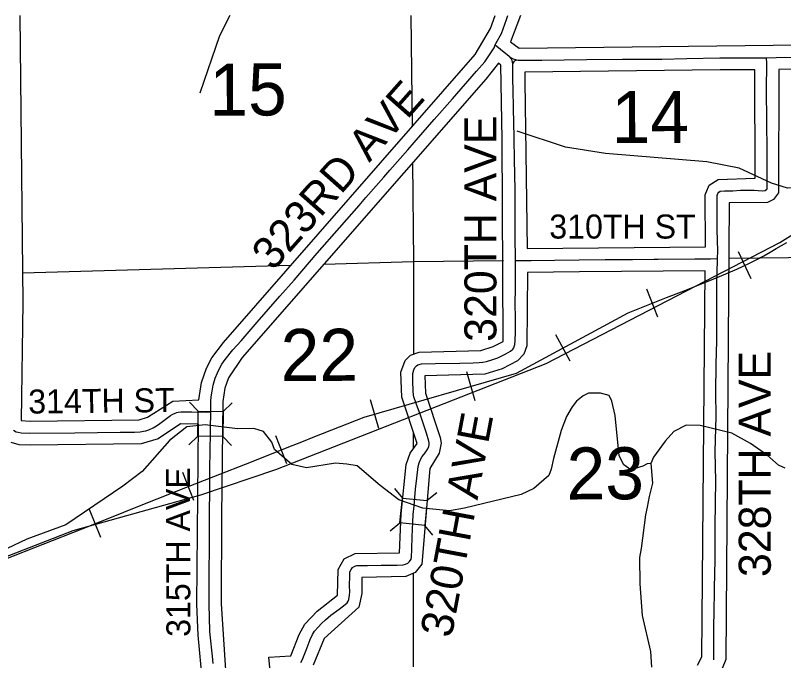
# Model space of a CAD drawing. Extents: x 10133 to 81668, y 7924 to 11018.
# Drawn here: x 11756.3 to 12044.1, y 9353.2 to 9594.9 of the extents above; entities that cross this region are included whole.
import ezdxf

# ---------------------------------------------------------------- set-up
doc = ezdxf.new("R2010")
doc.units = 0
for name, color, linetype in [('tdCoCityStreetMajor', 7, 'Continuous'), ('tdCoCityStreetMinor', 7, 'Continuous'), ('tdCoHydroRiver', 7, 'Continuous'), ('tdCoPriNonDiv', 7, 'Continuous'), ('tdCoRRCL', 7, 'Continuous'), ('tdCoRROwnerTxt', 7, 'Continuous'), ('tdCoSecRteBand', 7, 'Continuous'), ('tdCoShieldCoRte', 7, 'Continuous'), ('tdCoShieldStRte', 7, 'Continuous'), ('tdCoStrucNonDivPri', 7, 'Continuous')]:
    doc.layers.add(name, color=color, linetype=linetype)

msp = doc.modelspace()

# ---------------------------------------------------------------- linework, layer by layer
at = {"layer": 'tdCoCityStreetMajor'}
for points in [[(12019.3, 9503.87), (12019.38, 9506.61), (12019.18, 9514.65), (12019.13, 9517.56), (12019.21, 9525.57), (12019.18, 9527.39), (12019.38, 9528.13), (12019.8, 9528.73), (12020.32, 9529.02), (12021.89, 9529.17), (12025, 9529.22), (12027.98, 9529.37), (12033.04, 9529.39), (12036.05, 9529.22), (12037.18, 9529.24), (12037.87, 9529.89), (12037.87, 9533.71), (12037.97, 9543.79), (12037.82, 9555.48), (12037.8, 9559.8), (12037.68, 9562.51), (12037.65, 9566.98), (12037.77, 9576.89), (12037.68, 9579.04)], [(11997.05, 9503.55), (12010.83, 9503.68), (12016.68, 9503.73), (12019.3, 9503.87)], [(12017.89, 9353.47), (12017.95, 9353.59), (12017.95, 9357.36), (12017.9, 9367.37), (12018.02, 9370.26), (12018.12, 9380.47), (12018.37, 9390.82), (12018.42, 9403.11), (12018.59, 9412.53), (12018.66, 9420.37), (12018.49, 9431.46), (12018.81, 9444.66), (12018.74, 9453.66), (12018.79, 9464.19), (12019.01, 9472.92), (12019.01, 9475.51), (12019.03, 9486.09), (12019.03, 9494.72), (12019.28, 9503.08), (12019.3, 9503.87)]]:
    msp.add_lwpolyline(points, dxfattribs=at)
at = {"layer": 'tdCoCityStreetMinor'}
for points in [[(11936.07, 9583.87), (11936.59, 9583.37), (11937.95, 9582.21), (11941.22, 9579.57), (11941.5, 9579.37), (11942.06, 9578.96), (11942.75, 9578.64), (11943.67, 9578.32), (11944.65, 9578.14)], [(11942.65, 9576.8), (11942.33, 9578.06), (11942.01, 9578.73), (11941.5, 9579.37)], [(11944.65, 9578.14), (11953.53, 9578.12), (11961.84, 9578.27), (11970.25, 9578.39), (11983.74, 9578.51), (11998.39, 9578.54), (12007.83, 9578.73), (12020.21, 9578.96), (12029.14, 9578.96), (12037.68, 9579.04), (12041.27, 9579.08), (12052.91, 9579.33)], [(11943.6, 9503.01), (11943.59, 9504.42), (11943.54, 9511.06), (11943.51, 9517.15), (11943.51, 9525.29), (11943.46, 9529.53), (11943.27, 9540.9), (11943.19, 9548.59), (11943.02, 9555.22), (11942.9, 9559.39), (11942.7, 9567.9), (11942.67, 9570.05), (11942.62, 9576.41), (11942.65, 9576.8)], [(11944.65, 9578.14), (11943.78, 9578.01), (11943.19, 9577.71), (11942.87, 9577.32), (11942.65, 9576.8)], [(11863.17, 9352.41), (11863.73, 9353.3), (11865.16, 9357.13), (11866.69, 9361.14), (11867.56, 9362.9), (11868.32, 9364.15), (11869.68, 9365.73), (11870.96, 9367.11), (11872.42, 9368.44), (11874.41, 9370.15), (11877.54, 9372.46), (11879.79, 9374.24), (11880.55, 9374.83), (11881, 9375.4), (11881.24, 9376.09), (11881.42, 9377.64), (11881.59, 9378.95), (11881.49, 9381.22), (11881.54, 9384.97), (11881.59, 9386.42), (11882.01, 9387.36), (11882.53, 9388.07), (11883.39, 9388.54), (11884.23, 9388.79), (11886.32, 9388.76), (11888.15, 9388.86), (11893.28, 9388.91), (11899.27, 9388.99), (11901.51, 9389.06), (11902.43, 9389.28), (11903.24, 9389.65), (11903.96, 9390.34), (11904.5, 9391.16), (11904.65, 9391.87), (11904.77, 9395.08), (11904.92, 9399.52), (11905.16, 9404.99), (11905.34, 9407.95), (11905.66, 9411.13), (11906.22, 9417.35), (11906.67, 9421.56), (11907.14, 9425.93), (11907.48, 9427.33), (11908.12, 9428.79), (11908.72, 9429.6), (11909.78, 9431.06), (11910.84, 9432.56), (11911.18, 9433.43), (11911.23, 9434.07), (11911.26, 9434.78), (11911.18, 9435.45), (11910.27, 9438.36), (11909.13, 9441.76), (11908, 9445.16), (11906.45, 9449.55), (11905.58, 9452.04), (11905.44, 9452.64), (11905.29, 9454.21), (11905.16, 9457.89), (11905.21, 9460.8), (11905.51, 9462.08), (11905.88, 9462.94), (11906.5, 9463.66), (11907.06, 9463.98), (11908.4, 9464.37), (11913.62, 9464.52), (11922.77, 9464.67), (11927.75, 9464.72), (11930.07, 9464.82), (11931.4, 9464.94), (11932.81, 9465.29), (11934.81, 9465.8), (11937.05, 9466.67), (11939.96, 9468.05), (11941.81, 9469.13), (11942.67, 9469.82), (11943.04, 9470.39), (11943.41, 9471.62), (11943.56, 9473.03), (11943.61, 9476.33), (11943.64, 9480.31), (11943.56, 9488.05), (11943.59, 9491.45), (11943.59, 9498.65), (11943.61, 9501.81), (11943.6, 9503.01)], [(11943.6, 9503.01), (11944.5, 9503.04), (11949.55, 9503.06), (11958.23, 9503.23), (11967.5, 9503.38), (11977.2, 9503.43), (11987.48, 9503.46), (11995.57, 9503.53), (11997.05, 9503.55)], [(11755.61, 9439.46), (11756.57, 9438.94), (11757.29, 9438.72), (11758.42, 9438.47), (11761.72, 9438.37), (11778.52, 9438.55), (11795.58, 9438.72), (11800.96, 9438.79), (11803.08, 9438.94), (11804.31, 9439.11), (11805.15, 9439.31), (11806.31, 9439.66), (11807.89, 9440.4), (11809.1, 9441.09), (11810.4, 9442.02), (11814.42, 9444.98), (11815.24, 9445.45), (11816.13, 9445.87), (11816.77, 9446.17), (11817.31, 9446.31), (11818.2, 9446.34), (11822.34, 9446.39), (11827.96, 9446.24), (11829.45, 9446.36)]]:
    msp.add_lwpolyline(points, dxfattribs=at)
at = {"layer": 'tdCoHydroRiver'}
for points in [[(11836.55, 9594.91), (11832.8, 9587.19), (11825.38, 9565.74)], [(12135.52, 9516.46), (12101.18, 9517.02), (12090.23, 9520.13), (12087.1, 9522.92), (12082.76, 9527.34), (12076.25, 9533.38), (12074.35, 9534.05), (12058.07, 9530.68), (12045.53, 9530.21), (12039.58, 9532), (12027.4, 9537.69), (12015.28, 9540.08), (11977.33, 9543.18), (11962.37, 9545.51), (11944.27, 9551.57)], [(11994.37, 9426.98), (11992.95, 9426.96), (11991.31, 9425.98), (11986.83, 9424.71), (11984.19, 9426.56), (11982.48, 9429.84), (11981.02, 9444.97), (11979.73, 9450.4), (11978.75, 9452.51), (11975.42, 9453.4), (11970.92, 9453.31), (11969.04, 9452.33), (11966.47, 9450.39), (11964.86, 9448.23), (11962.79, 9444.64), (11960.75, 9439.39), (11957.87, 9428.92), (11956.99, 9424.88), (11956.09, 9422.5), (11950.5, 9417.66), (11945.8, 9415.44), (11924.58, 9410.32), (11918.92, 9409.27), (11908.95, 9410.27), (11899.9, 9413.42), (11892.94, 9418.74), (11884.28, 9426.16), (11880.48, 9426.8), (11876.21, 9427.2), (11865.35, 9425.34), (11859.88, 9426.66), (11853.38, 9432.23), (11852.39, 9435.05), (11849.23, 9439.02), (11845.66, 9440.14), (11839.51, 9440.02), (11827.39, 9441.54), (11820.53, 9440.75), (11813.98, 9435.7), (11803.76, 9423.99), (11796.51, 9418.47), (11775.19, 9404.04)], [(12044.6, 9425.29), (12042.21, 9426.43), (12037.88, 9430.14), (12031.64, 9434.53), (12024.7, 9438.43), (12012.81, 9441.29), (12007.6, 9441.43), (12002.91, 9438.98), (11999.66, 9435.37), (11995.27, 9429.37), (11994.37, 9426.98)], [(11994.37, 9426.98), (11994.97, 9419.65), (11993.65, 9414.66), (11993.01, 9410.62), (11992.35, 9407.77), (11990.69, 9395.18), (11990.04, 9391.86), (11990.22, 9381.92), (11991.14, 9370.09), (11994.23, 9356.65), (11994.57, 9350.74)], [(11775.19, 9404.04), (11760.54, 9398.66), (11753.23, 9395.15)]]:
    msp.add_lwpolyline(points, dxfattribs=at)
at = {"layer": 'tdCoPriNonDiv'}
for points in [[(11757.98, 9594.91), (11759.05, 9487.31), (11758.38, 9443.09), (11761.77, 9442.87)], [(11761.77, 9442.87), (11802.61, 9443.42), (11805.81, 9444.39), (11815.23, 9450.39), (11825.05, 9450.82), (11825.94, 9457.4), (11827.83, 9462.74), (11829.84, 9466.63), (11834.21, 9472.38), (11928.55, 9580.28), (11934.25, 9589.99), (11935.97, 9594.91)], [(11945.48, 9594.91), (11941.74, 9584.93), (11945.05, 9582.64), (12093.14, 9584.37), (12096.46, 9582.2), (12098.43, 9577.84), (12098.5, 9550.47), (12143.88, 9534.24), (12147.33, 9531.26), (12149.76, 9526.52), (12150.09, 9514.39), (12150.75, 9511.79), (12152.8, 9510.22), (12156.77, 9510.07)], [(11852.11, 9345.49), (11851.26, 9354.45), (11859.5, 9355.03), (11862.57, 9362.94), (11864.68, 9366.8), (11869.38, 9371.76), (11876.89, 9377.69), (11877.17, 9387.27), (11879.41, 9391.32), (11883.61, 9393.25), (11900.21, 9393.52), (11900.85, 9408.21), (11902.71, 9426.71), (11904.15, 9430.89), (11906.74, 9434.56), (11901, 9451.88), (11900.73, 9461.19), (11902.26, 9465.61), (11904.28, 9467.58), (11907.49, 9468.78), (11930.66, 9469.39), (11935.28, 9470.8), (11939, 9472.7), (11938.69, 9548.51), (11938.13, 9576.29), (11937.21, 9577.03), (11932.47, 9571.02), (11841.18, 9466.68), (11836.09, 9459.16), (11834.7, 9455.29), (11834.02, 9450.21), (11833.43, 9407.45), (11833.31, 9374.4), (11835.29, 9345.87)], [(12089.49, 9575.58), (12042.25, 9574.6), (12042.13, 9528.43), (12040.24, 9525.95), (12038, 9524.82), (12023.7, 9524.7), (12022.45, 9353.59), (12019.9, 9347.44)], [(12014.84, 9508.21), (12014.69, 9527.64), (12016.13, 9531.33), (12019.52, 9533.45), (12033.38, 9533.88), (12033.25, 9574.5), (12020.25, 9574.46), (11947.14, 9573.64), (11947.17, 9570.09), (11948.06, 9507.55), (12014.84, 9508.21)], [(12011.86, 9351.46), (12013.45, 9354.65), (12014.66, 9499.21), (11967.55, 9498.88), (11948.08, 9498.56), (11947.89, 9471.15), (11946.81, 9467.93), (11944.36, 9465.43), (11938.67, 9462.47), (11932.15, 9460.51), (11909.7, 9459.91), (11909.88, 9453.4), (11915.47, 9436.79), (11915.75, 9434.63), (11915.01, 9430.89), (11911.58, 9425.15), (11908.58, 9389.26), (11906.08, 9386.16), (11902.58, 9384.69), (11886.03, 9384.27), (11886.05, 9378.36), (11884.94, 9373.23), (11871.97, 9361.5), (11867.83, 9351.43)], [(11826.31, 9345.27), (11824.74, 9362.69), (11824.31, 9374.34), (11824.88, 9441.82), (11818.12, 9441.84), (11809.8, 9436.32), (11803.39, 9434.45), (11761.77, 9433.88), (11757.74, 9434.03), (11754.7, 9434.85)]]:
    msp.add_lwpolyline(points, dxfattribs=at)
at = {"layer": 'tdCoRRCL'}
for p, q in [((12031.96, 9496.17), (12027.13, 9506.33)), ((11996.9, 9481.82), (11992.78, 9492.29)), ((11964.05, 9465.31), (11958.69, 9475.21)), ((11928.52, 9450.51), (11925.4, 9461.32)), ((11892.49, 9440.11), (11889.37, 9450.92)), ((11857.98, 9426.92), (11853.84, 9437.38)), ((11823.09, 9413.12), (11818.98, 9423.59)), ((11788.26, 9399.3), (11784.1, 9409.75))]:
    msp.add_line(p, q, dxfattribs=at)
for points in [[(11853.85, 9424.76), (11955.16, 9464.46), (12042.66, 9509.8), (12052.01, 9515.67), (12061.58, 9522.5), (12072.55, 9530.3), (12083.53, 9537.39), (12093.84, 9542.81), (12103.67, 9548.69), (12114.38, 9557.43), (12165.55, 9591.63)], [(11752.05, 9391.05), (11766.65, 9396.81), (11781.26, 9402.57), (11791.7, 9406.72), (11802.14, 9410.87), (11809.42, 9413.76), (11816.69, 9416.65), (11823.65, 9419.38), (11830.61, 9422.11), (11844.69, 9427.7), (11858.76, 9433.28), (11863.61, 9435.18), (11868.45, 9437.09), (11877.71, 9440.73), (11886.96, 9444.37), (11943.95, 9460.82), (11985.85, 9483.51), (12000.16, 9489.15), (12005.79, 9491.38), (12011.41, 9493.6), (12015.75, 9495.33), (12020.1, 9497.06), (12023.3, 9498.43), (12026.51, 9499.81), (12028.91, 9500.95), (12031.31, 9502.09), (12033.98, 9503.45), (12036.65, 9504.8), (12038.99, 9506.16), (12041.33, 9507.52), (12043.32, 9508.68), (12045.3, 9509.84)], [(11777.93, 9401.93), (11825.78, 9415.28), (11853.85, 9424.76)], [(11577.07, 9299.13), (11594.5, 9308.16), (11635.99, 9337.16), (11654.28, 9348.37), (11675.39, 9360.38), (11686.92, 9365.1), (11711.76, 9376.15), (11777.93, 9401.93)]]:
    msp.add_lwpolyline(points, dxfattribs=at)
at = {"layer": 'tdCoSecRteBand'}
msp.add_lwpolyline([(11830.37, 9352.11), (11830.07, 9354.89), (11829.23, 9362.86), (11829.18, 9364.21), (11828.81, 9374.32), (11828.84, 9385.08), (11828.96, 9396.79), (11828.94, 9407.47), (11829.06, 9417.97), (11829.16, 9426.48), (11829.28, 9430.33), (11829.35, 9440.05), (11829.45, 9446.36), (11829.45, 9446.61), (11829.53, 9450.43), (11829.65, 9452.03), (11829.95, 9454.13), (11830.32, 9456.35), (11831.15, 9458.98), (11831.99, 9461.03), (11832.91, 9462.83), (11833.67, 9464.26), (11834.88, 9465.96), (11837.74, 9469.59), (11840.85, 9473.02), (11846.91, 9480), (11855.37, 9489.71), (11860.67, 9495.75), (11869.38, 9505.77), (11877.71, 9515.31), (11885.06, 9523.65), (11887.58, 9526.63), (11894.34, 9534.3), (11896.55, 9536.86), (11903.31, 9544.48), (11905.73, 9547.22), (11913.18, 9555.93), (11920.06, 9563.64), (11929.08, 9573.98), (11932.14, 9577.55), (11933.84, 9580.09), (11935.59, 9582.73), (11936.07, 9583.87), (11936.28, 9584.36), (11938.35, 9588.11), (11940.3, 9593.39), (11940.77, 9594.91)], dxfattribs=at)
at = {"layer": 'tdCoShieldCoRte'}
for points in [[(11821.5, 9450.02), (11824.77, 9446.66), (11834.15, 9446.52)], [(11837.45, 9449.71), (11834.15, 9446.52), (11834.01, 9437.13)], [(11821.26, 9434.01), (11824.63, 9437.27), (11824.77, 9446.66)], [(11837.28, 9433.76), (11834.01, 9437.13), (11824.63, 9437.27)], [(11898.28, 9417.71), (11901.24, 9414.08), (11910.58, 9413.14)], [(11914.14, 9416.04), (11910.58, 9413.14), (11909.64, 9403.8)], [(11896.67, 9401.78), (11900.3, 9404.74), (11901.24, 9414.08)], [(11912.61, 9400.17), (11909.64, 9403.8), (11900.3, 9404.74)]]:
    msp.add_lwpolyline(points, dxfattribs=at)
at = {"layer": 'tdCoStrucNonDivPri'}
msp.add_line((11904.46, 9594.91), (11904.88, 9553.2), dxfattribs=at)
for points in [[(11905.02, 9539.64), (11905.4, 9502.64)], [(12023.85, 9503.93), (12057.01, 9504.3)], [(11758.97, 9498.41), (11859.52, 9501.32)], [(11871.79, 9501.67), (11905.4, 9502.64)], [(11905.4, 9502.64), (11905.37, 9468.13)], [(11905.4, 9502.64), (11939.11, 9503.01)], [(11905.34, 9438.75), (11905.33, 9432.58)], [(11905.28, 9385.73), (11905.25, 9350.86)]]:
    msp.add_lwpolyline(points, dxfattribs=at)

# ---------------------------------------------------------------- texts
at = {"layer": 'tdCoRROwnerTxt'}
for s, rotation, p in [('15', 0.23, (11828.96, 9557.32)), ('14', 0.2307, (11979.63, 9547.03)), ('22', 0.23, (11855.68, 9457.9)), ('23', 0.2307, (11962.79, 9413.52))]:
    msp.add_text(s, height=19.5, rotation=rotation, dxfattribs=at).set_placement(p)
at = {"layer": 'tdCoShieldStRte'}
for s, height, rotation, p in [('323RD AVE', 12, 48.5, (11852.8, 9498.82)), ('320TH AVE', 12, 90, (11936.49, 9472.62)), ('328TH AVE', 12, 90, (12039.27, 9384.5)), ('314TH ST', 9, 0.6223, (11761.14, 9445.71)), ('320TH AVE', 12, 79.3247, (11919.64, 9361.39)), ('315TH AVE', 9, 90.1472, (11821.84, 9362.08))]:
    msp.add_text(s, height=height, rotation=rotation, dxfattribs=at).set_placement(p)
msp.add_text('310TH ST', height=9, dxfattribs=at).set_placement((11956.29, 9511.29))

doc.saveas('drawing.dxf')
